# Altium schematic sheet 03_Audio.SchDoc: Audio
size A3; Date: 3/31/2015; Author: P.A.; CompanyName: STMicroelectronics; Organization: Microcontrollers Division; Address1: 12, Rue Jules HOROWITZ; Address2: 38019 Grenoble; Address3: FRANCE; DocumentNumber: 6; Revision: E-01; SheetNumber: 6; SheetTotal: 12; Project: STM32F413H-DISCO
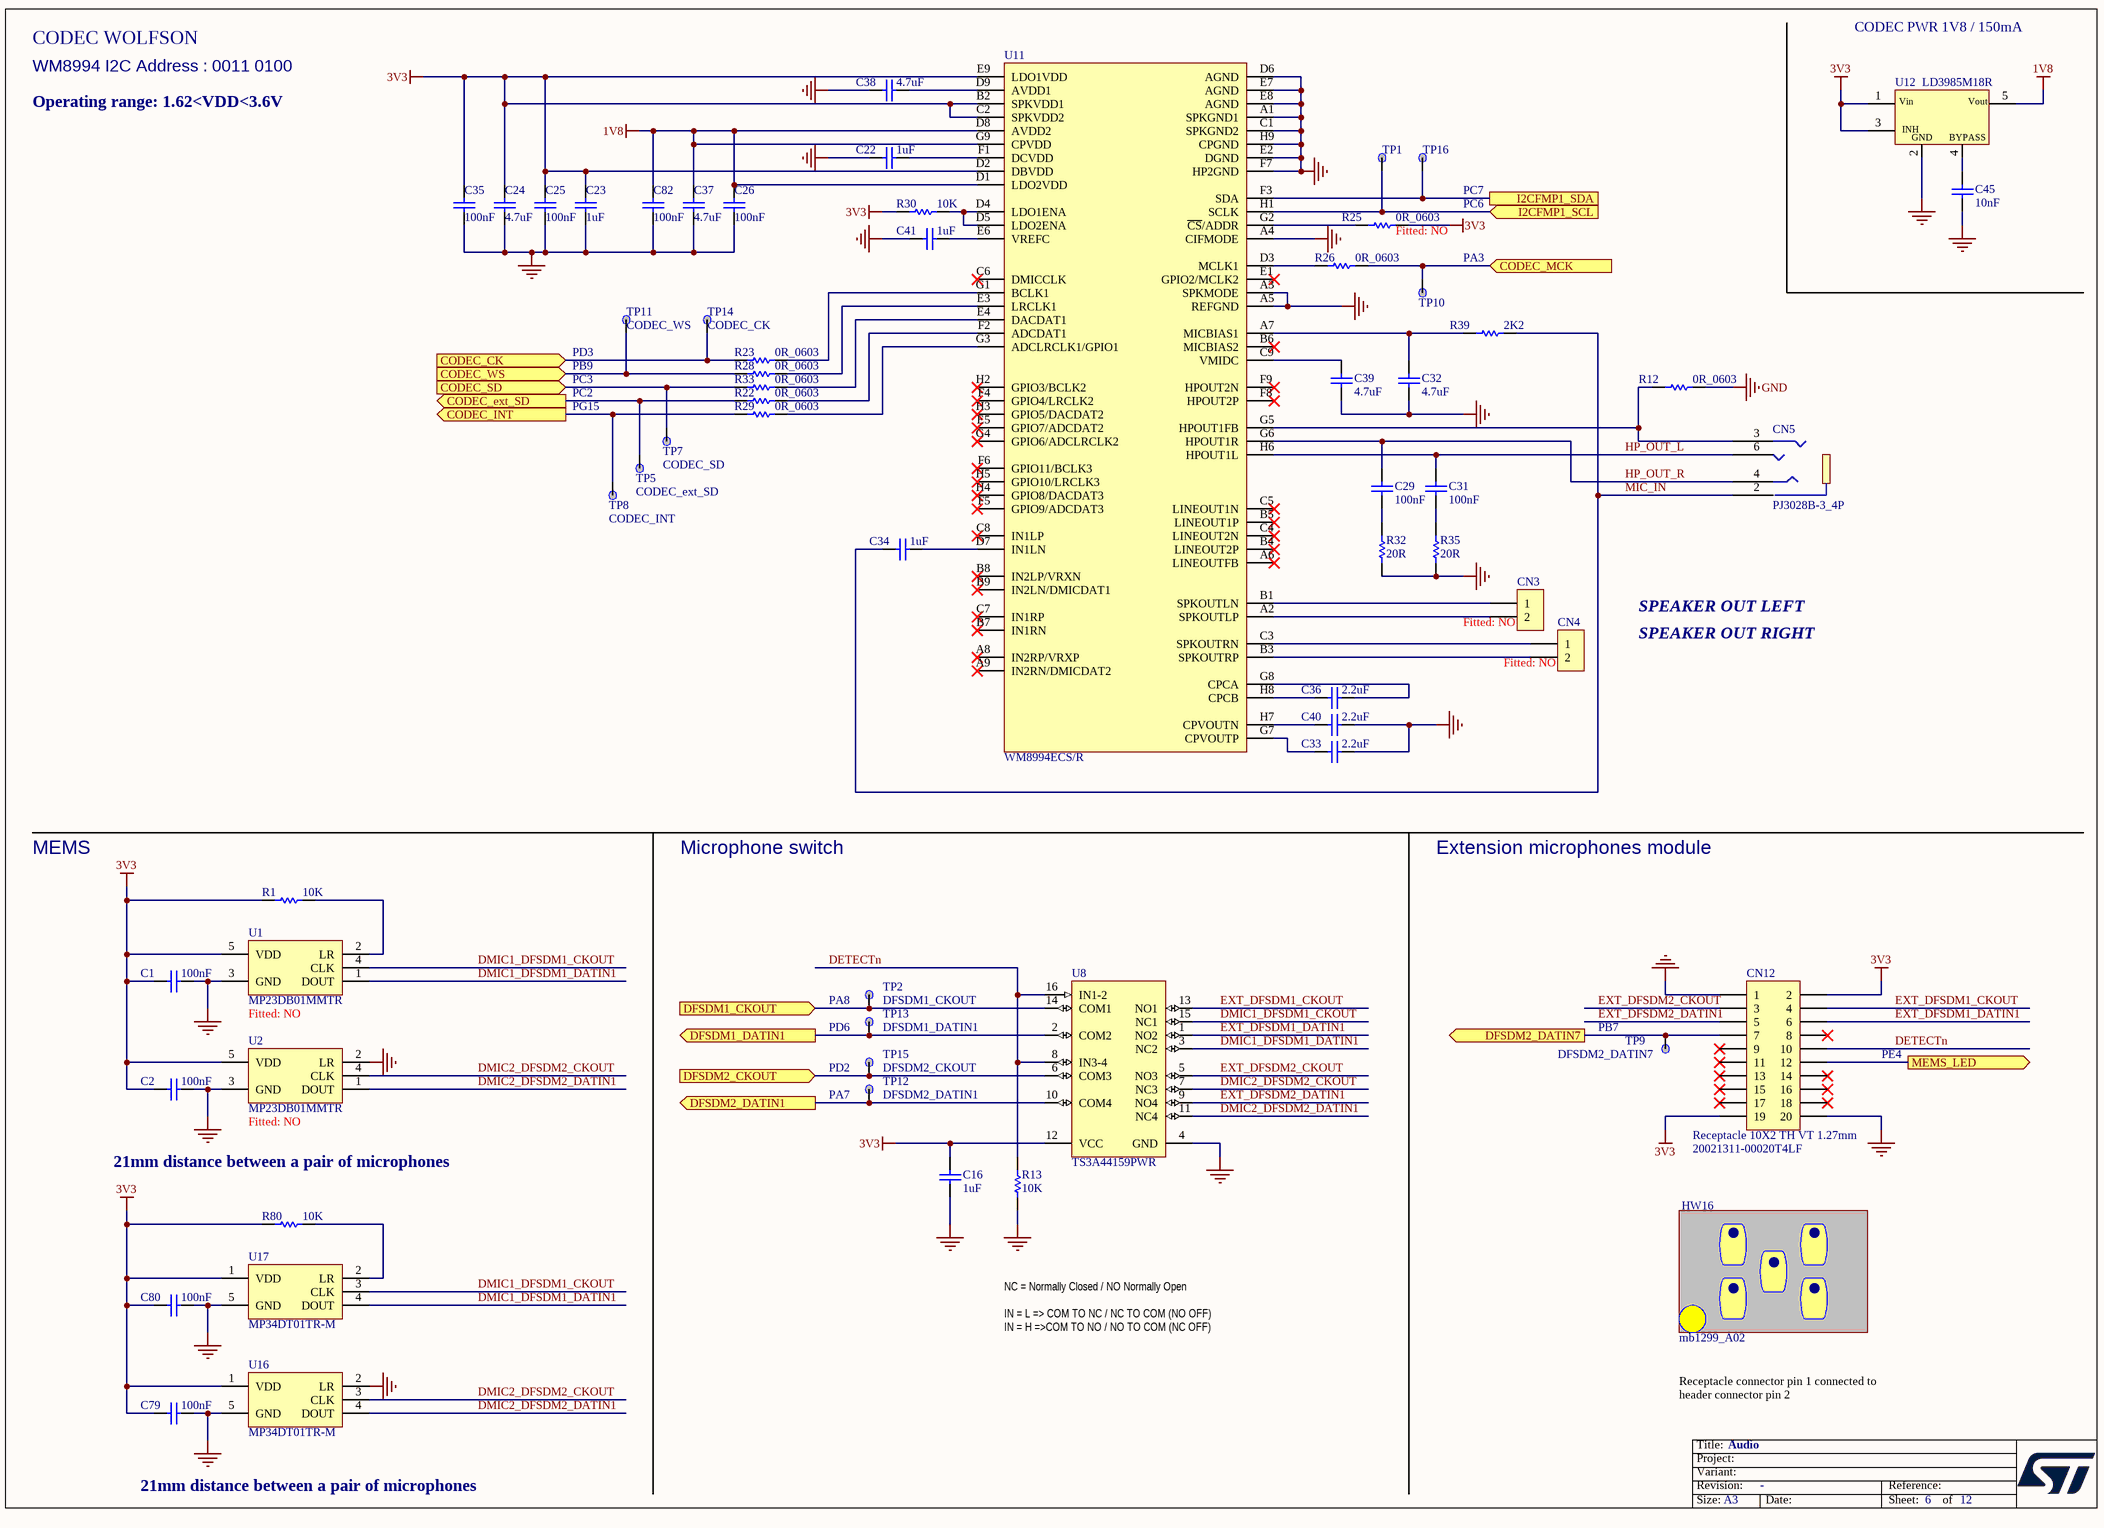
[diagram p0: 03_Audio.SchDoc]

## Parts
C1  100nF  [C0402]
C2  100nF  [C0402]
C16  1uF  [C0603]
C22  1uF  [C0603]
C23  1uF  [C0603]
C24  4.7uF  [C0603]
C25  100nF  [C0402]
C26  100nF  [C0402]
C29  100nF  [C0402]
C31  100nF  [C0402]
C32  4.7uF  [C0603]
C33  2.2uF  [C0603]
C34  1uF  [C0603]
C35  100nF  [C0402]
C36  2.2uF  [C0603]
C37  4.7uF  [C0603]
C38  4.7uF  [C0603]
C39  4.7uF  [C0603]
C40  2.2uF  [C0603]
C41  1uF  [C0603]
C45  10nF  [C0402]
C79  100nF  [C0402]
C80  100nF  [C0402]
C82  100nF  [C0402]
CN3  Fitted: NO  [CON_SAMTEC_TSW-102-07-G-S]  (hidden comment: header 2 pins 2.54mm)
CN4  Fitted: NO  [CON_SAMTEC_TSW-102-07-G-S]  (hidden comment: header 2 pins 2.54mm)
CN5  PJ3028B-3_4P  [CON_PHONE-JACK-3P5_HY_PJ3028B]
CN12  Receptacle 10X2 TH VT 1.27mm  Order_Code: 20021311-00020T4LF  [CON_FCI_20021311-XXX20XXLF_MOD-MB1299]
HW16  mb1299_A02  (mechanical)
R1  10K  [R0402]
R12  0R_0603  [R0603]
R13  10K  [R0402]
R22  0R_0603  [R0603]
R23  0R_0603  [R0603]
R25  0R_0603  Fitted: NO  [R0603]
R26  0R_0603  [R0603]
R28  0R_0603  [R0603]
R29  0R_0603  [R0603]
R30  10K  [R0402]
R32  20R  [R0402]
R33  0R_0603  [R0603]
R35  20R  [R0402]
R39  2K2  [R0402]
R80  10K  [R0402]
TP1  TP  [TP_SMD_1MM]  (value not drawn)
TP2  value DFSDM1_CKOUT  [TP_SMD_1MM]  (hidden comment: TP)
TP5  value CODEC_ext_SD  [TP_SMD_1MM]  (hidden comment: TP)
TP7  value CODEC_SD  [TP_SMD_1MM]  (hidden comment: TP)
TP8  value CODEC_INT  [TP_SMD_1MM]  (hidden comment: TP)
TP9  value DFSDM2_DATIN7  [TP_SMD_1MM]  (hidden comment: TP)
TP10  TP  [TP_SMD_1MM]  (value not drawn)
TP11  value CODEC_WS  [TP_SMD_1MM]  (hidden comment: TP)
TP12  value DFSDM2_DATIN1  [TP_SMD_1MM]  (hidden comment: TP)
TP13  value DFSDM1_DATIN1  [TP_SMD_1MM]  (hidden comment: TP)
TP14  value CODEC_CK  [TP_SMD_1MM]  (hidden comment: TP)
TP15  value DFSDM2_CKOUT  [TP_SMD_1MM]  (hidden comment: TP)
TP16  TP  [TP_SMD_1MM]  (value not drawn)
U1  MP23DB01MMTR  Fitted: NO  [MIC_STM_MP23DB01MMTR]
U2  MP23DB01MMTR  Fitted: NO  [MIC_STM_MP23DB01MMTR]
U8  TS3A44159PWR  [ICC_TSSOP16_5P1X4P5_P065]
U11  WM8994ECS/R  [ICC_W-CSP-BGA72_4P511X4P023_P050]
U12  LD3985M18R  [REG_SOT23-5L]
U16  MP34DT01TR-M  [MIC_HCLGA_3X4X1_4LD]
U17  MP34DT01TR-M  [MIC_HCLGA_3X4X1_4LD]

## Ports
CODEC_CK (in), CODEC_ext_SD (out), CODEC_INT (out), CODEC_MCK (in), CODEC_SD (in), CODEC_WS (in), DFSDM1_CKOUT (in), DFSDM1_DATIN1 (out), DFSDM2_CKOUT (in), DFSDM2_DATIN1 (out), DFSDM2_DATIN7 (out), I2CFMP1_SCL (in), I2CFMP1_SDA, MEMS_LED (out)

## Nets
1V8: C26.2 C37.2 C82.2 U11.D1(LDO2VDD) U11.D8(AVDD2) U11.G9(CPVDD) U12.5(Vout)
3V3: C1.2 C2.2 C16.2 C23.2 C24.2 C25.2 C35.2 C79.2 C80.2 CN12.2 CN12.19 R1.1 R25.2 R30.1 R80.1 U1.5(VDD) U2.5(VDD) U8.12(VCC) U11.B2(SPKVDD1) U11.C2(SPKVDD2) U11.D2(DBVDD) U11.E9(LDO1VDD) U12.1(Vin) U12.3(CE) U16.1(VDD) U17.1(VDD)
GND: C1.1 C2.1 C16.1 C22.1 C23.1 C24.1 C25.1 C26.1 C32.1 C33.2 C35.1 C37.1 C38.1 C39.1 C40.2 C41.1 C45.1 C79.1 C80.1 C82.1 CN12.1 CN12.20 R12.2 R13.1 R32.1 R35.1 U1.3(GND) U2.2(LR) U2.3(GND) U8.4(GND) U11.A1(SPKGND1) U11.A3(SPKMODE) U11.A4(CIFMODE) U11.A5(REFGND) U11.C1(SPKGND2) U11.D6(AGND) U11.E2(DGND) U11.E7(AGND) U11.E8(AGND) U11.F7(HP2GND) U11.H9(CPGND) U12.2(GND) U16.2(LR) U16.5(GND) U17.5(GND)
CODEC_CK: R23.1 TP14.1 ; port CODEC_CK
CODEC_ext_SD: R22.1 TP5.1 ; port CODEC_ext_SD
CODEC_INT: R29.1 TP8.1 ; port CODEC_INT
CODEC_MCK: R26.2 TP10.1 ; port CODEC_MCK
CODEC_SD: R33.1 TP7.1 ; port CODEC_SD
CODEC_WS: R28.1 TP11.1 ; port CODEC_WS
DETECTn: CN12.10 R13.2 U8.8(IN3-4) U8.16(IN1-2)
DFSDM1_CKOUT: TP2.1 U8.14(COM1) ; port DFSDM1_CKOUT
DFSDM1_DATIN1: TP13.1 U8.2(COM2) ; port DFSDM1_DATIN1
DFSDM2_CKOUT: TP15.1 U8.6(COM3) ; port DFSDM2_CKOUT
DFSDM2_DATIN1: TP12.1 U8.10(COM4) ; port DFSDM2_DATIN1
DFSDM2_DATIN7: CN12.7 TP9.1 ; port DFSDM2_DATIN7
DMIC1_DFSDM1_CKOUT: U1.4(CLK) U8.15(NC1) U17.3(CLK)
DMIC1_DFSDM1_DATIN1: U1.1(DOUT) U8.3(NC2) U17.4(DOUT)
DMIC2_DFSDM2_CKOUT: U2.4(CLK) U8.7(NC3) U16.3(CLK)
DMIC2_DFSDM2_DATIN1: U2.1(DOUT) U8.11(NC4) U16.4(DOUT)
EXT_DFSDM1_CKOUT: CN12.4 U8.13(NO1)
EXT_DFSDM1_DATIN1: CN12.6 U8.1(NO2)
EXT_DFSDM2_CKOUT: CN12.3 U8.5(NO3)
EXT_DFSDM2_DATIN1: CN12.5 U8.9(NO4)
HP_OUT_L: C31.2 CN5.6 U11.H6(HPOUT1L)
HP_OUT_R: C29.2 CN5.4 U11.G6(HPOUT1R)
I2CFMP1_SCL: TP1.1 U11.H1(SCLK) ; port I2CFMP1_SCL
I2CFMP1_SDA: TP16.1 U11.F3(SDA) ; port I2CFMP1_SDA
MEMS_LED: CN12.12 ; port MEMS_LED
MIC_IN: C34.1 CN5.2 R39.2
NetC22_2: C22.2 U11.F1(DCVDD)
NetC29_1: C29.1 R32.2
NetC31_1: C31.1 R35.2
NetC32_2: C32.2 R39.1 U11.A7(MICBIAS1)
NetC33_1: C33.1 U11.G7(CPVOUTP)
NetC34_2: C34.2 U11.D7(IN1LN)
NetC36_1: C36.1 U11.H8(CPCB)
NetC36_2: C36.2 U11.G8(CPCA)
NetC38_2: C38.2 U11.D9(AVDD1)
NetC39_2: C39.2 U11.C9(VMIDC)
NetC40_1: C40.1 U11.H7(CPVOUTN)
NetC41_2: C41.2 U11.E6(VREFC)
NetC45_2: C45.2 U12.4(BYPASS)
NetCN3_1: CN3.1 U11.B1(SPKOUTLN)
NetCN3_2: CN3.2 U11.A2(SPKOUTLP)
NetCN4_1: CN4.1 U11.C3(SPKOUTRN)
NetCN4_2: CN4.2 U11.B3(SPKOUTRP)
NetCN5_3: CN5.3 R12.1 U11.G5(HPOUT1FB)
NetR1_2: R1.2 U1.2(LR)
NetR22_2: R22.2 U11.F2(ADCDAT1)
NetR23_2: R23.2 U11.G1(BCLK1)
NetR25_1: R25.1 U11.G2(~{CS}/ADDR)
NetR26_1: R26.1 U11.D3(MCLK1)
NetR28_2: R28.2 U11.E3(LRCLK1)
NetR29_2: R29.2 U11.G3(ADCLRCLK1/GPIO1)
NetR30_2: R30.2 U11.D4(LDO1ENA) U11.D5(LDO2ENA)
NetR33_2: R33.2 U11.E4(DACDAT1)
NetR80_2: R80.2 U17.2(LR)

Not connected (* = marked no-connect by the designer): CN12 8* 9* 11* 13* 14* 15* 16* 17* 18*; U11 A6(LINEOUTFB)* A8(IN2RP/VRXP)* A9(IN2RN/DMICDAT2)* B4(LINEOUT2P)* B5(LINEOUT1P)* B6(MICBIAS2)* B7(IN1RN)* B8(IN2LP/VRXN)* B9(IN2LN/DMICDAT1)* C4(LINEOUT2N)* C5(LINEOUT1N)* C6(DMICCLK)* C7(IN1RP)* C8(IN1LP)* E1(GPIO2/MCLK2)* E5(GPIO7/ADCDAT2)* F4(GPIO4/LRCLK2)* F5(GPIO9/ADCDAT3)* F6(GPIO11/BCLK3)* F8(HPOUT2P)* F9(HPOUT2N)* G4(GPIO6/ADCLRCLK2)* H2(GPIO3/BCLK2)* H3(GPIO5/DACDAT2)* H4(GPIO8/DACDAT3)* H5(GPIO10/LRCLK3)*

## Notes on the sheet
- CODEC WOLFSON
- CODEC PWR 1V8 / 150mA
- Operating range: 1.62<VDD<3.6V
- WM8994 I2C Address : 0011 0100
- PC6
- PC7
- PA3
- (near TP11) PD3
- PB9
- PC3
- PG15
- PC2
- SPEAKER OUT RIGHT
- SPEAKER OUT LEFT
- MEMS
- Microphone switch
- Extension microphones module
- PA8
- PD6
- (near TP9) PB7
- PE4
- PD2
- PA7
- 21mm distance between a pair of microphones
- NC = Normally Closed / NO Normally Open
  IN = L => COM TO NC / NC TO COM (NO OFF)
  IN = H =>COM TO NO / NO TO COM (NC OFF)
- Receptacle connector pin 1 connected to header connector pin 2

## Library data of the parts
C1 C2 C25 C26 C29 C31 C35 C79 C80 C82 = Cap_100nF_X7R_10%_0402: Capacitor,100nF,16V,X7R,10%,0402,YAGEO; Manuf_Part_1: CC0402KRX7R7BB104; Fitted: YES; Ordered_By: Subcon
C16 C22 C23 C34 C41 = Cap_1uF_X5R_10%_0603: Capacitor,1uF,16V,X5R,10%,0603,YAGEO; Manuf_Part_1: CC0603KRX5R7BB105; Fitted: YES; Ordered_By: Subcon
C24 C32 C37-C39 = Cap_4.7uF_X5R_10%_0603: Capacitor,4.7uF,16V, X5R,10%,0603,YAGEO; Manuf_Part_1: CC0603KRX5R7BB475; Fitted: YES; Order_Code: CC0603KRX5R7BB105; Ordered_By: subcon
C33 C36 C40 = Cap_2.2uF_X5R_10%_0603: Capacitor,2.2uF,10V, X5R,10%,0603,YAGEO; Manuf_Part_1: CC0603KRX5R6BB225; Manuf_Part_2: C0603C225K8PACTU; Manuf_2: KEMET; Fitted: YES; Ordered_By: Subcon
C45 = Cap_10nF_X7R_10%_0402: Capacitor,10nF,16V,X7R,10%,0402,YAGEO; Manuf_Part_1: CC0402KRX7R7BB103; Fitted: YES; Ordered_By: Subcon
CN3 CN4 = Header 2 pins: Manuf_1: SAMTEC; Manuf_Part_2: 4711955140470; Manuf_2: KONTEC; Manuf_Part_1: TSW-102-07-x-S; Order_Code: 423-2841; Ordered_By: Subcon
CN5 = MCD-00263: Connector Jack Stereo 3.5mm, female SMT, 4 PIN; Provided_By: Subcon
CN12 = Receptacle 10X2 TH VT 1.27mm: 20 Position Receptacle Connector 0.050" (1.27mm) Through Hole Vertical Mount; Manuf_1: AMPHEMOL_FCI; Fitted: YES; Ordered_By: Subcon
HW16 = mb1299_MEMS_Module: mb1299_MEMS module; Ordered_By: Subcon; Fitted: YES
R1 R13 R30 R80 = Res_10K_1%_0402: Resistor,10K,0402,1%,YAGEO; Manuf_Part_1: RC0402FR-0710KL; Fitted: YES; Ordered_By: subcon
R12 R22 R23 R26 R28 R29 R33 = Res_0_5%_0603: Resistor,0R,0603,5%,YAGEO; Manuf_Part_1: RC0603JR-070RL; Fitted: YES; Order_Code: 2363481; Ordered_By: subcon
R25 = Res_0_5%_0603: Resistor,0R,0603,5%,YAGEO; Manuf_Part_1: RC0603JR-070RL; Order_Code: 2363481; Ordered_By: subcon
R32 R35 = Res_20_1%_0402: Resistor,20R,0402,1%,YAGEO; Manuf_Part_1: RC0402FR-0720RL; Fitted: Yes; Ordered_By: Subcon
R39 = Res_2K2_1%_0402: Resistor,2K2,0402,1%,YAGEO; Manuf_Part_1: RC0402FR-072K2L; Fitted: YES; Ordered_By: Subcon
TP1 = TP 1mm: Test Point; Fitted: YES; Ordered_By: Subcon; Value: I2CFMP1_SCL
TP2 TP5 TP7-TP9 TP11-TP15 = TP 1mm: Test Point; Fitted: YES; Ordered_By: Subcon
TP10 = TP 1mm: Test Point; Fitted: YES; Ordered_By: Subcon; Value: CODEC_MCK
TP16 = TP 1mm: Test Point; Fitted: YES; Ordered_By: Subcon; Value: I2CFMP1_SDA
U1 U2 = MP23DB01MMTR: MEMS audio sensor, omnidirectional digital microphone; Manuf_1: STM; Ref St: 9188010; ECCN_US/EU: EAR99/NEC
U8 = TS3A44159PWR: SPDT analog switch 4-Channel 2:1 bidirectional; Manuf_1: TI; Fitted: YES; ECCN_US/EU: EAR99/NEC; Order_Code: 1755573; Ordered_By: Subcon
U11 = WM8994ECS/R: Multi-Channel Audio Hub CODEC for Smartphones; Manuf_1: Cirrus Logic; ECCN_US/EU: EAR99/NEC; Fitted: YES; Ordered_By: Subcon
U12 = LD3985M18R: Ultra low drop-low noise BiCMOS voltage, regulators low ESR capacitors compatible; Manuf_1: STM; ECCN_US/EU: EAR99/NEC; Fitted: YES
U16 U17 = MP34DT01TR-M: MEMS audio sensor, omnidirectional digital microphone; Manuf_1: STM; Ref St: 9188008; ECCN_US/EU: EAR99/NEC; Fitted: YES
